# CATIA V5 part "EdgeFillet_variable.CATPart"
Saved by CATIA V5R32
Part number: Part1
Bounding box of the stored display mesh (mm): x -55 to 55, y -155 to 25.782, z -44.572 to 40
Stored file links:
  D:\PROJECTS\Project 2022\CATIA V5 6R 2022\Resources\Part Files\c17_catia_v6_6r2022_prt\EdgeFillet_variable.CATPart
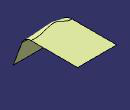
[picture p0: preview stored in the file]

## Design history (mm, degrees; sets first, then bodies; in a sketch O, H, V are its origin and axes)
Body1 (main body)
  Sketch1 on yz-plane, origin (0, 0, 0), H (0, 1, 0), V (0, 0, 1)
    point P1 (25.7818, 40)
    line L1 (25.7818, 40) -> (-124.2182, 40)
    line L2 (-124.2182, 40) -> (-155, -44.5723)
    point P3 (-155, -44.5723)
    length L1 = 150
    length L2 = 90
    angle L2 L1 = 110
    distance P1 H = 40
    distance P3 V = 155
    horizontal: L1 H
  Extrude1: Element1 Sketch1, Lim1 55, Lim2 55
  Plane1: type Offset, RefPlane yz-plane, Offset 20
  Point1: type OnCurve, Support edge [face of Extrude1 from Sketch1.L1 | face of Extrude1 from Sketch1.L2], Length 0
  Fillet1: radius 20, on edge [face of Extrude1 from Sketch1.L1 | face of Extrude1 from Sketch1.L2]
